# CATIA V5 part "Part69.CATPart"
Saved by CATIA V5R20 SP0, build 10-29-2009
Part number: FA 053000-1
Revision: ANY
Definition: UNKNOWN
Nomenclature: FA 053000-1
Source: Unknown
Bounding box of the stored display mesh (mm): x -1.9 to 1.9, y -1.1 to 2.45, z -1.9 to 1.9
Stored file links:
  C:\Users\Utente\Desktop\IO LAVORO\3D X SITO CF\CUMSA\3D files FA\FA 053000\Part69.CATPart

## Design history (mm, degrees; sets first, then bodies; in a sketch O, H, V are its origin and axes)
Body1 "Cortar-Extruir1" (main body)
  Solid1: solid without history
